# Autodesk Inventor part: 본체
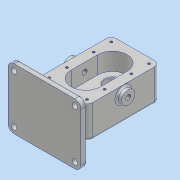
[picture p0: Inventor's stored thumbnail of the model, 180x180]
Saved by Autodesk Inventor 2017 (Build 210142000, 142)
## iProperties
Part Number: 본체
Material: 알루미늄 6061
Document SubType Name: Modeling
Designer: MRC
Density: 2.7 g/cm^3
Appearance: 알루미늄 - 평지
Mass: 1472.54 g
Surface Area: 818.394 cm^2
Volume: 545.387 cm^3
Author: MRC
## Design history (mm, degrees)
sketch "스케치1"
  geometry: L1 (-40, -60)-(40, -60); L2 (40, -60)-(40, 60); L3 (40, 60)-(-40, 60); L4 (-40, 60)-(-40, -60); L5 (-40, -60)-(40, 60); L6 (40, -60)-(-40, 60); 1 further point
  constraints: 12 end point, 2 midpoint, 2 parallel, 1 horizontal, 1 perpendicular
  dimensions: "d0" = 80 distance of L2.end L3.end; "d1" = 120 distance of L1.end L2.end
extrude "돌출1" new body sketch "스케치1" distance "d2" = 14; taper "d3" = 0 deg; dims "d8" = 39, "d9" = 0
sketch "스케치3"
  geometry: L1 (0, -22)-(0, 22); L2 (-24, -22)-(-24, 22); L3 (24, 22)-(24, -22); A1 r 24 centre (0, -22) between (-24, -22) and (24, -22); A2 r 24 centre (0, 22) between (24, 22) and (-24, 22); 1 further point
  constraints: 8 end point, 4 point on circle, 4 tangent, 2 centre point, 1 midpoint, 1 parallel, 1 vertical
  dimensions: "d13" = 44 distance of L3.start L3.end; "d14" = 48 distance between parallel lines of L3 L2
extrude "돌출2" cut sketch "스케치3" distance "d15" = 29; taper "d16" = 0 deg
sketch "스케치4"
  geometry: C1 r 12.5 at (0, -22); C2 r 12.5 at (0, 22); A1 r 24 centre (0, -22) between (-24, -22) and (24, -22) reference; A2 r 24 centre (0, 22) between (24, 22) and (-24, 22) reference; 1 further point
  constraints: 2 centre point, 2 coincident
  dimensions: "d17" = 25 diameter of C1; "d18" = 25 diameter of C2
extrude "돌출3" cut sketch "스케치4" distance "d19" = 15; taper "d20" = 0 deg
sketch "스케치5"
  geometry: C1 r 12.5 at (0, 22) reference; C2 r 19 at (0, 22); 1 further point
  constraints: 1 centre point, 1 coincident
  dimensions: "d21" = 38 diameter of C2
extrude "돌출4" join sketch "스케치5" distance "d22" = 17; taper "d23" = 0 deg
sketch "스케치6"
  geometry: C1 r 19 at (0, 0) reference; C2 r 14 at (0, 0); 1 further point
  constraints: 1 centre point, 1 coincident
  dimensions: "d24" = 28 diameter of C2
extrude "돌출5" cut sketch "스케치6" distance "d25" = 7.3; taper "d26" = 0 deg
sketch "스케치7"
  geometry: C1 r 14 at (0, 0) reference; C2 r 8.5 at (0, 0); 1 further point
  constraints: 1 centre point, 1 coincident
  dimensions: "d27" = 17 diameter of C2
extrude "돌출6" cut sketch "스케치7" stored distance "d28" = 7.3; taper "d29" = 0 deg
fillet "모깎기1" dims "d30" = 9
sketch "스케치8"
  geometry: A1 r 9 centre (31, -51) between (31, -60) and (40, -51) reference; A2 r 9 centre (31, 51) between (40, 51) and (31, 60) reference; A3 r 9 centre (-31, 51) between (-31, 60) and (-40, 51) reference; A4 r 9 centre (-31, -51) between (-40, -51) and (-31, -60) reference; A5 r 24 centre (0, -22) between (-24, -22) and (24, -22) reference; A6 r 24 centre (0, 22) between (24, 22) and (-24, 22) reference; 9 further points
  constraints: 4 coincident, 4 vertical alignment, 2 horizontal alignment
  dimensions: "d31" = 44 distance of point (31, 22) point (31, -22); "d32" = 22 vertical distance of point (0, 0) point (31, 22); "d33" = 29 distance of point (31, 51) point (31, 22); "d34" = 44 distance of point (-31, 22) point (-31, -22)
hole "구멍1" sketch "스케치8" at (-31, -51), (31, -51), (-31, 51), (31, 51), (-31, 22), (31, 22), (-31, -22), (31, -22) diameter "d35" = 4.134; stored, may be unused: countersink angle "d39" = 90 deg, drill point angle "d41" = 118 deg; dims "d36" = 10, "d37" = 4, "d38" = 2, "d40" = 12
sketch "스케치10"
  geometry: C1 r 11 at (-39, 51); 1 further point
  constraints: 1 centre point, 1 coincident
  dimensions: "d42" = 22 diameter of C1
extrude "돌출7" join sketch "스케치10" distance "d43" = 8; taper "d44" = 0 deg
sketch "스케치11"
  geometry: C1 r 11 at (0, 0) reference; 1 further point
  constraints: 1 coincident
hole "구멍2" sketch "스케치11" at (0, 0) diameter "d45" = 8.376; stored, may be unused: countersink angle "d49" = 90 deg, drill point angle "d51" = 118 deg; dims "d46" = 20, "d47" = 4, "d48" = 2, "d50" = 27.3
fillet "모깎기2" dims "d52" = 3
fillet "모깎기3" dims "d53" = 3
node "작업 평면1"
sketch "스케치12"
  geometry: L1 (-19, -56)-(19, -56) reference; L2 (60, 44)-(-60, 44); L3 (-60, 44)-(-60, -56); L4 (-60, -56)-(60, -56); L5 (60, -56)-(60, 44); 2 further points
  constraints: 8 end point, 2 parallel, 1 collinear, 1 horizontal, 1 midpoint, 1 perpendicular, 1 vertical alignment
  dimensions: "d55" = 100 distance of L4.end L2.start; "d56" = 120 distance of L2.start L2.end
extrude "돌출8" join sketch "스케치12" distance "d57" = 10; taper "d58" = 0 deg
fillet "모깎기4" dims "d65" = 0.5
chamfer "모따기2" distance "d66" = 1; stored, may be unused: second distance "d67" = 2, angle "d68" = 45 deg
fillet "모깎기5" dims "d69" = 10
fillet "모깎기6" dims "d70" = 3
fillet "모깎기7" dims "d71" = 3
fillet "모깎기8" dims "d72" = 3
sketch "스케치15"
  geometry: C1 r 4.5 at (-50, -34); C2 r 4.5 at (-50, 46); C3 r 4.5 at (50, 46); C4 r 4.5 at (50, -34); A1 r 7 centre (50, -34) between (50, -41) and (57, -34) reference; A2 r 7 centre (50, 46) between (57, 46) and (50, 53) reference; A3 r 7 centre (-50, 46) between (-50, 53) and (-57, 46) reference; A4 r 7 centre (-50, -34) between (-57, -34) and (-50, -41) reference; 1 further point
  constraints: 4 centre point, 4 coincident
  dimensions: "d73" = 9 diameter of C1; "d74" = 9 diameter of C2; "d75" = 9 diameter of C3; "d76" = 9 diameter of C4
extrude "돌출9" cut sketch "스케치15" stored distance "d77" = 10; taper "d78" = 0 deg
chamfer "모따기3" distance "d79" = 0.7; stored, may be unused: second distance "d80" = 2, angle "d81" = 30 deg
sketch "스케치17"
  geometry: L1 (-80, -39)-(-60, -27.453); L2 (-80, 14)-(-60, 2.453); L3 (-60, -36)-(-60, 14) reference; L4 (-80, 34)-(-80, -46) reference; L5 (-83, -56)-(-90, -56) reference; 1 further point
  constraints: 4 end point, 4 point on line
  dimensions: "d82" = 17 distance from line of L1.start L5; "d83" = 53 distance of L2.start L1.start; "d84" = 60 deg angle of L1 L4; "d85" = 60 deg angle of L2 L4
extrude "돌출10" join sketch "스케치17" stored distance "d86" = 48; taper "d87" = 0 deg
fillet "모깎기9" dims "d88" = 3
fillet "모깎기10" dims "d89" = 3
sketch "스케치18"
  geometry: L1 (-60, 46)-(-60, -34) reference; L2 (-50, -44)-(50, -44) reference; 2 further points
  constraints: 1 other
  dimensions: "d90" = 60 distance from line of L1 point (0, -34); "d91" = 10 distance from line of point (0, -34) L2
feature "엠보싱1" sketch "스케치18" dims "d0" = 80, "d1" = 120, "d92" = 0.5, "d93" = 0
node "솔리드1"
mirror "미러1"
node "투영된 루프1"
